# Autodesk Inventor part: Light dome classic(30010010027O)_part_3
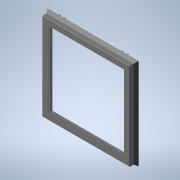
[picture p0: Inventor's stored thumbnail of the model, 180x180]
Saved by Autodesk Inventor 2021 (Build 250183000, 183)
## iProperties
Created: 2026-04
Part Number: Light dome classic(30010010027O)_part_3
Material: Generic
Catalog Web Link: www.3dfindit.com
Description: Light dome classic_part_3-
Vendor: KINGSPAN
Document SubType Name: Modeling
Designer: psAdmin
Manufacturer: KINGSPAN
Mass: 8135.61 g
Surface Area: 12543.2 cm^2
Volume: 8135.61 cm^3
Density: 1 g/cm^3
Appearance: PSOLRGB-255-255-255
Category: PARTsolutions
Company: KINGSPAN
Title: Light dome classic(30010010027O)_part_3
Author: Cadenas PARTsolutions
PSOL_IDENT_0: {$CADENAS_DATA/23d-libs/kingspan_kla/light_dome_classic/parts/part_3.prj},259 {VTYP=3D},{NB=Light do
PSOL_IDENT_1: me classic(30010010027O)_part_3},{LINA=Light dome classic(30010010027O)_part_3},{NN=Light dome class
PSOL_IDENT_2: ic_part_3},{DATE=20.03.2025 09:30:52},{GEOMDATE=28.06.2024 08:53:13},{VERSION=},{LINEID=10},{WBVAR=L
PSOL_IDENT_3: ODLEVEL,L,W,DP,OP,OC},{WBNUMERIC=W}  {NB=Light dome classic(30010010027O)_part_3},{LINA=Light dome c
PSOL_IDENT_4: lassic(30010010027O)_part_3},{KT=DUMMY},{IDNR=},{PN=Light dome classic},{LODLEVEL=300},{L=100},{W=10
PSOL_IDENT_5: 0},{DRIVE=1},{WX=100,150,200,250,300},{DP=2},{OP=7},{OPX='7','24/48 V OPEN/CLOSE including ventilati
PSOL_IDENT_6: on function'},{LX=1000},{XWX=1000},{OC=O}
NB: Light dome classic(30010010027O)_part_3
NN: Light dome classic_part_3
NBSYN: $PN.($LODLEVEL.$L.$W.$DP.$OP.$OC.)_part_3
LINA: Light dome classic(30010010027O)_part_3
CATALOG: Light + Air
PN: Light dome classic
LODLEVEL: 300
L: 100
W: 100
DP: NSHEV (natural smoke, heat exhaust ventilation)
OP: 24/48 V OPEN/CLOSE including ventilation function
OC: Open
SUPPLIER: KINGSPAN
ARTICLENO: Light dome classic(30010010027O)_part_3
BOMINFO: Light dome classic(30010010027O)_part_3
CREATOR: CADENAS GmbH
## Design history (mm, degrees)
sketch "Sketch_1"
  geometry: L1 (-402, 72.096)-(-402, 75.446); L2 (-402, 75.446)-(-457, 75.446); L3 (-462, 70.446)-(-462, 35.573); L4 (-463.71, 29.981)-(-483.061, 1.292); L5 (-481.277, 0.21)-(-478.348, 2.69); L6 (-478.348, 2.69)-(-479.115, 3.207); L7 (-479.115, 3.207)-(-462, 28.582); L8 (-462, 28.582)-(-462, 17.946); L9 (-462, 17.946)-(-411.5, 17.946); L10 (-411.5, 17.946)-(-411.5, 40.446); L11 (-411.5, 40.446)-(-435, 40.446); L12 (-435, 40.446)-(-435, 72.096); L13 (-435, 72.096)-(-402, 72.096); A1 r 5 centre (-457, 70.446) between (-457, 75.446) and (-462, 70.446); A2 r 10 centre (-472, 35.573) between (-463.71, 29.981) and (-462, 35.573); A3 r 1.1 centre (-481.988, 1.05) between (-483.061, 1.292) and (-481.277, 0.21)
  constraints: 26 end point, 6 point on circle, 3 centre point
extrude "Extrusion1" join sketch "Sketch_1" stored distance "d0" = 2000; taper "d1" = 0 deg
sketch "Sketch_2"
  geometry: L1 (402, 75.446)-(402, 72.096); L2 (402, 72.096)-(435, 72.096); L3 (435, 72.096)-(435, 40.446); L4 (435, 40.446)-(411.5, 40.446); L5 (411.5, 40.446)-(411.5, 17.946); L6 (411.5, 17.946)-(462, 17.946); L7 (462, 17.946)-(462, 28.582); L8 (462, 28.582)-(479.115, 3.207); L9 (479.115, 3.207)-(478.348, 2.69); L10 (478.348, 2.69)-(481.277, 0.21); L11 (483.061, 1.292)-(463.71, 29.981); L12 (462, 35.573)-(462, 70.446); L13 (457, 75.446)-(402, 75.446); A1 r 1.1 centre (481.988, 1.05) between (481.277, 0.21) and (483.061, 1.292); A2 r 10 centre (472, 35.573) between (462, 35.573) and (463.71, 29.981); A3 r 5 centre (457, 70.446) between (462, 70.446) and (457, 75.446)
  constraints: 26 end point, 6 point on circle, 3 centre point
extrude "Extrusion2" join sketch "Sketch_2" stored distance "d2" = 2000; taper "d3" = 0 deg
sketch "Sketch_3"
  geometry: L1 (483.061, 1.292)-(463.71, 29.981); L2 (462, 35.573)-(462, 70.446); L3 (457, 75.446)-(402, 75.446); L4 (402, 75.446)-(402, 72.096); L5 (402, 72.096)-(432, 72.096); L6 (432, 72.096)-(432, 40.446); L7 (432, 40.446)-(411.5, 40.446); L8 (411.5, 40.446)-(411.5, 17.946); L9 (411.5, 17.946)-(462, 17.946); L10 (462, 17.946)-(462, 28.582); L11 (462, 28.582)-(479.115, 3.207); L12 (479.115, 3.207)-(478.348, 2.69); L13 (478.348, 2.69)-(481.277, 0.21); A1 r 1.1 centre (481.988, 1.05) between (481.277, 0.21) and (483.061, 1.292); A2 r 10 centre (472, 35.573) between (462, 35.573) and (463.71, 29.981); A3 r 5 centre (457, 70.446) between (462, 70.446) and (457, 75.446)
  constraints: 26 end point, 6 point on circle, 3 centre point
extrude "Extrusion3" join sketch "Sketch_3" stored distance "d4" = 2000; taper "d5" = 0 deg
sketch "Sketch_4"
  geometry: L1 (-402, 75.446)-(-457, 75.446); L2 (-462, 70.446)-(-462, 35.573); L3 (-463.71, 29.981)-(-483.061, 1.292); L4 (-481.277, 0.21)-(-478.348, 2.69); L5 (-478.348, 2.69)-(-479.115, 3.207); L6 (-479.115, 3.207)-(-462, 28.582); L7 (-462, 28.582)-(-462, 17.946); L8 (-462, 17.946)-(-411.5, 17.946); L9 (-411.5, 17.946)-(-411.5, 40.446); L10 (-411.5, 40.446)-(-435, 40.446); L11 (-435, 40.446)-(-435, 72.096); L12 (-435, 72.096)-(-402, 72.096); L13 (-402, 72.096)-(-402, 75.446); A1 r 5 centre (-457, 70.446) between (-457, 75.446) and (-462, 70.446); A2 r 10 centre (-472, 35.573) between (-463.71, 29.981) and (-462, 35.573); A3 r 1.1 centre (-481.988, 1.05) between (-483.061, 1.292) and (-481.277, 0.21)
  constraints: 26 end point, 6 point on circle, 3 centre point
extrude "Extrusion4" join sketch "Sketch_4" stored distance "d6" = 2000; taper "d7" = 0 deg
sketch "Sketch_5"
  geometry: L1 (-402, 125.446)-(-1000, 125.446); L2 (-1000, 125.446)-(-1000, -63.554); L3 (-1000, -63.554)-(-491.002, -63.554); L4 (-491.002, -63.554)-(-491.002, -31.506); L5 (-492.031, -29.546)-(-462, 13.947); L6 (-462, 13.947)-(-462, 70.446); L7 (-457, 75.446)-(-402, 75.446); L8 (-402, 75.446)-(-402, 125.446); A1 r 1.25 centre (-491.002, -30.256) between (-492.031, -29.546) and (-491.002, -31.506); A2 r 5 centre (-457, 70.446) between (-457, 75.446) and (-462, 70.446)
  constraints: 16 end point, 4 point on circle, 2 centre point
extrude "Extrusion5" cut sketch "Sketch_5" stored distance "d8" = 2000; taper "d9" = 0 deg
sketch "Sketch_6"
  geometry: L1 (1000, 125.446)-(402, 125.446); L2 (402, 125.446)-(402, 75.446); L3 (402, 75.446)-(457, 75.446); L4 (462, 70.446)-(462, 13.947); L5 (462, 13.947)-(492.031, -29.546); L6 (491.002, -31.506)-(491.002, -63.554); L7 (491.002, -63.554)-(1000, -63.554); L8 (1000, -63.554)-(1000, 125.446); A1 r 5 centre (457, 70.446) between (462, 70.446) and (457, 75.446); A2 r 1.25 centre (491.002, -30.256) between (491.002, -31.506) and (492.031, -29.546)
  constraints: 16 end point, 4 point on circle, 2 centre point
extrude "Extrusion6" cut sketch "Sketch_6" stored distance "d10" = 2000; taper "d11" = 0 deg
sketch "Sketch_7"
  geometry: L1 (1000, 125.446)-(402, 125.446); L2 (402, 125.446)-(402, 75.446); L3 (402, 75.446)-(457, 75.446); L4 (462, 70.446)-(462, 13.947); L5 (462, 13.947)-(492.031, -29.546); L6 (491.002, -31.506)-(491.002, -63.554); L7 (491.002, -63.554)-(1000, -63.554); L8 (1000, -63.554)-(1000, 125.446); A1 r 5 centre (457, 70.446) between (462, 70.446) and (457, 75.446); A2 r 1.25 centre (491.002, -30.256) between (491.002, -31.506) and (492.031, -29.546)
  constraints: 16 end point, 4 point on circle, 2 centre point
extrude "Extrusion7" cut sketch "Sketch_7" stored distance "d12" = 2000; taper "d13" = 0 deg
sketch "Sketch_8"
  geometry: L1 (-1000, 125.446)-(-1000, -63.554); L2 (-1000, -63.554)-(-491.002, -63.554); L3 (-491.002, -63.554)-(-491.002, -31.506); L4 (-492.031, -29.546)-(-462, 13.947); L5 (-462, 13.947)-(-462, 70.446); L6 (-457, 75.446)-(-402, 75.446); L7 (-402, 75.446)-(-402, 125.446); L8 (-402, 125.446)-(-1000, 125.446); A1 r 1.25 centre (-491.002, -30.256) between (-492.031, -29.546) and (-491.002, -31.506); A2 r 5 centre (-457, 70.446) between (-457, 75.446) and (-462, 70.446)
  constraints: 16 end point, 4 point on circle, 2 centre point
extrude "Extrusion8" cut sketch "Sketch_8" stored distance "d14" = 2000; taper "d15" = 0 deg
sketch "Sketch_9"
  geometry: L1 (-457, 35.995)-(-457, 39.929); L2 (-457, 39.929)-(-483.061, 1.292); L3 (-481.277, 0.21)-(-478.348, 2.69); L4 (-478.348, 2.69)-(-479.115, 3.207); L5 (-479.115, 3.207)-(-457, 35.995); A1 r 1.1 centre (-481.988, 1.05) between (-483.061, 1.292) and (-481.277, 0.21)
  constraints: 10 end point, 2 point on circle, 1 centre point
extrude "Extrusion9" join sketch "Sketch_9" stored distance "d16" = 2000; taper "d17" = 0 deg
sketch "Sketch_10"
  geometry: L1 (457, 39.929)-(457, 35.995); L2 (457, 35.995)-(479.115, 3.207); L3 (479.115, 3.207)-(478.348, 2.69); L4 (478.348, 2.69)-(481.277, 0.21); L5 (483.061, 1.292)-(457, 39.929); A1 r 1.1 centre (481.988, 1.05) between (481.277, 0.21) and (483.061, 1.292)
  constraints: 10 end point, 2 point on circle, 1 centre point
extrude "Extrusion10" join sketch "Sketch_10" stored distance "d18" = 2000; taper "d19" = 0 deg
sketch "Sketch_11"
  geometry: L1 (483.061, 1.292)-(457, 39.929); L2 (457, 39.929)-(457, 35.995); L3 (457, 35.995)-(479.115, 3.207); L4 (479.115, 3.207)-(478.348, 2.69); L5 (478.348, 2.69)-(481.277, 0.21); A1 r 1.1 centre (481.988, 1.05) between (481.277, 0.21) and (483.061, 1.292)
  constraints: 10 end point, 2 point on circle, 1 centre point
extrude "Extrusion11" join sketch "Sketch_11" stored distance "d20" = 2000; taper "d21" = 0 deg
sketch "Sketch_12"
  geometry: L1 (-457, 39.929)-(-483.061, 1.292); L2 (-481.277, 0.21)-(-478.348, 2.69); L3 (-478.348, 2.69)-(-479.115, 3.207); L4 (-479.115, 3.207)-(-457, 35.995); L5 (-457, 35.995)-(-457, 39.929); A1 r 1.1 centre (-481.988, 1.05) between (-483.061, 1.292) and (-481.277, 0.21)
  constraints: 10 end point, 2 point on circle, 1 centre point
extrude "Extrusion12" join sketch "Sketch_12" stored distance "d22" = 2000; taper "d23" = 0 deg
sketch "Sketch_13"
  geometry: L1 (-462, 42.516)-(-1481.988, 42.516); L2 (-1481.988, 42.516)-(-1481.988, -3.554); L3 (-1481.988, -3.554)-(-481.988, -3.554); L4 (-481.988, -3.554)-(-481.988, -0.05); L5 (-483.061, 1.292)-(-462, 32.516); L6 (-462, 32.516)-(-462, 42.516); A1 r 1.1 centre (-481.988, 1.05) between (-483.061, 1.292) and (-481.988, -0.05)
  constraints: 12 end point, 2 point on circle, 1 centre point
extrude "Extrusion13" cut sketch "Sketch_13" stored distance "d24" = 2000; taper "d25" = 0 deg
sketch "Sketch_14"
  geometry: L1 (1481.988, -3.554)-(1481.988, 42.516); L2 (1481.988, 42.516)-(462, 42.516); L3 (462, 42.516)-(462, 32.516); L4 (462, 32.516)-(483.061, 1.292); L5 (481.988, -0.05)-(481.988, -3.554); L6 (481.988, -3.554)-(1481.988, -3.554); A1 r 1.1 centre (481.988, 1.05) between (481.988, -0.05) and (483.061, 1.292)
  constraints: 12 end point, 2 point on circle, 1 centre point
extrude "Extrusion14" cut sketch "Sketch_14" stored distance "d26" = 2000; taper "d27" = 0 deg
sketch "Sketch_15"
  geometry: L1 (1481.988, 42.516)-(462, 42.516); L2 (462, 42.516)-(462, 32.516); L3 (462, 32.516)-(483.061, 1.292); L4 (481.988, -0.05)-(481.988, -3.554); L5 (481.988, -3.554)-(1481.988, -3.554); L6 (1481.988, -3.554)-(1481.988, 42.516); A1 r 1.1 centre (481.988, 1.05) between (481.988, -0.05) and (483.061, 1.292)
  constraints: 12 end point, 2 point on circle, 1 centre point
extrude "Extrusion15" cut sketch "Sketch_15" stored distance "d28" = 2000; taper "d29" = 0 deg
sketch "Sketch_16"
  geometry: L1 (-1481.988, 42.516)-(-1481.988, -3.554); L2 (-1481.988, -3.554)-(-481.988, -3.554); L3 (-481.988, -3.554)-(-481.988, -0.05); L4 (-483.061, 1.292)-(-462, 32.516); L5 (-462, 32.516)-(-462, 42.516); L6 (-462, 42.516)-(-1481.988, 42.516); A1 r 1.1 centre (-481.988, 1.05) between (-483.061, 1.292) and (-481.988, -0.05)
  constraints: 12 end point, 2 point on circle, 1 centre point
extrude "Extrusion16" cut sketch "Sketch_16" stored distance "d30" = 2000; taper "d31" = 0 deg
sketch "Sketch_17"
  geometry: L1 (-17.946, 461.802)-(-17.946, 439.665); L2 (-17.946, 439.665)-(-17.214, 437.835); L3 (-17.214, 437.835)-(-15.357, 438.578); L4 (-15.357, 438.578)-(-15.946, 440.05); L5 (-15.946, 440.05)-(-15.946, 460.837); L6 (-15.946, 460.837)-(7.12, 479.184); L7 (6.644, 477.499)-(4.764, 476.817); L8 (5.875, 480.749)-(-17.946, 461.802); A1 r 1.5 centre (8.054, 478.01) between (6.644, 477.499) and (7.12, 479.184); A2 r 3.5 centre (8.054, 478.01) between (4.764, 476.817) and (5.875, 480.749)
  constraints: 16 end point, 4 point on circle, 2 centre point
extrude "Extrusion17" join sketch "Sketch_17" distance "d32" = 70; taper "d33" = 0 deg
sketch "Sketch_18"
  geometry: L1 (-17.946, 461.802)-(-17.946, 439.665); L2 (-17.946, 439.665)-(-17.214, 437.835); L3 (-17.214, 437.835)-(-15.357, 438.578); L4 (-15.357, 438.578)-(-15.946, 440.05); L5 (-15.946, 440.05)-(-15.946, 460.837); L6 (-15.946, 460.837)-(7.12, 479.184); L7 (6.644, 477.499)-(4.764, 476.817); L8 (5.875, 480.749)-(-17.946, 461.802); A1 r 1.5 centre (8.054, 478.01) between (6.644, 477.499) and (7.12, 479.184); A2 r 3.5 centre (8.054, 478.01) between (4.764, 476.817) and (5.875, 480.749)
  constraints: 16 end point, 4 point on circle, 2 centre point
extrude "Extrusion18" join sketch "Sketch_18" distance "d34" = 70; taper "d35" = 0 deg
sketch "Sketch_19"
  geometry: L1 (-15.946, 501.757)-(16.193, 463.455); L2 (16.193, 463.455)-(31.514, 476.311); L3 (31.514, 476.311)-(-0.625, 514.613); L4 (-0.625, 514.613)-(-15.946, 501.757)
  constraints: 8 end point
extrude "Extrusion19" cut sketch "Sketch_19" stored distance "d36" = 38; taper "d37" = 0 deg
sketch "Sketch_20"
  geometry: L1 (-15.946, 501.757)-(16.193, 463.455); L2 (16.193, 463.455)-(31.514, 476.311); L3 (31.514, 476.311)-(-0.625, 514.613); L4 (-0.625, 514.613)-(-15.946, 501.757)
  constraints: 8 end point
extrude "Extrusion20" cut sketch "Sketch_20" stored distance "d38" = 38; taper "d39" = 0 deg
sketch "Sketch_21"
  geometry: L1 (-499.411, -2.354)-(-477.41, -2.354); L2 (-477.41, -2.354)-(-477.41, 8.646); L3 (-477.41, 8.646)-(-475.722, 11.091); L4 (-475.722, 11.091)-(-481.711, 19.644); A1 r 20 centre (-481.411, -0.354) between (-481.711, 19.644) and (-501.411, -0.354); A2 r 2 centre (-499.411, -0.354) between (-501.411, -0.354) and (-499.411, -2.354)
  constraints: 8 end point, 4 point on circle, 2 centre point
extrude "Extrusion21" join sketch "Sketch_21" stored distance "d40" = 41; taper "d41" = 0 deg
node "IP_3_XY"
node "IP_3_YZ"
node "IP_3_ZX"
node "IP_3_X"
node "IP_3_Y"
node "IP_3_Z"
node "IP_3_Center"
node "IP_for_part_11_1_XY"
node "IP_for_part_11_1_YZ"
node "IP_for_part_11_1_ZX"
node "IP_for_part_11_1_X"
node "IP_for_part_11_1_Y"
node "IP_for_part_11_1_Z"
node "IP_for_part_11_1_Center"
node "IP_for_part_4_XY"
node "IP_for_part_4_YZ"
node "IP_for_part_4_ZX"
node "IP_for_part_4_X"
node "IP_for_part_4_Y"
node "IP_for_part_4_Z"
node "IP_for_part_4_Center"
node "IP_for_part_5_XY"
node "IP_for_part_5_YZ"
node "IP_for_part_5_ZX"
node "IP_for_part_5_X"
node "IP_for_part_5_Y"
node "IP_for_part_5_Z"
node "IP_for_part_5_Center"
node "IP_for_part_6_XY"
node "IP_for_part_6_YZ"
node "IP_for_part_6_ZX"
node "IP_for_part_6_X"
node "IP_for_part_6_Y"
node "IP_for_part_6_Z"
node "IP_for_part_6_Center"
body "Solid1"
other parameters: "d42" = 0, "d43" = 0
